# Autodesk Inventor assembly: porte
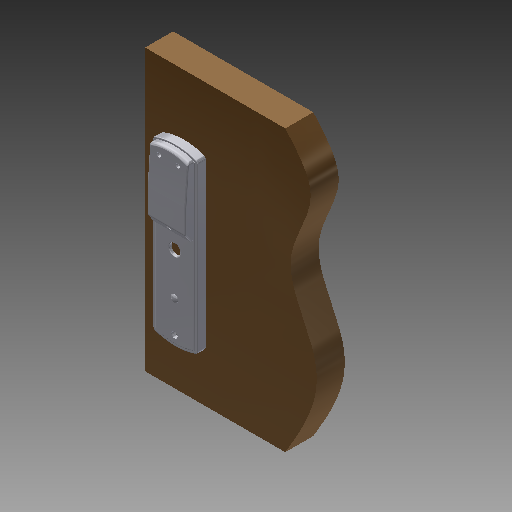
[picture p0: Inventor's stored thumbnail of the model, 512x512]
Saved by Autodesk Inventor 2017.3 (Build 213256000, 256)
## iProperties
Created: 2011-01
Part Number: porte
Material: Générique
Document SubType Name: Assembly
Designer: ficho
Author: ficho
Sending System: SolidWorks 2009
Last Author: christophe
Last Saved: 2011-02-11
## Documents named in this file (15)
- G:\travail\année 2019-2020\réforme\toussaint\Serrure biométrique SET\Documentations_pedagogique\Modelisation_Solidworks\porte.iam
- G:\travail\année 2019-2020\réforme\toussaint\Serrure biométrique SET\Documentations_pedagogique\Modelisation_Solidworks\capteur.iam
- G:\travail\année 2019-2020\réforme\toussaint\Serrure biométrique SET\Documentations_pedagogique\Modelisation_Solidworks\Assemblage9.iam
- G:\travail\année 2019-2020\réforme\toussaint\Serrure biométrique SET\Documentations_pedagogique\Modelisation_Solidworks\tetiere.iam
- G:\travail\année 2019-2020\réforme\toussaint\Serrure biométrique SET\Documentations_pedagogique\Modelisation_Solidworks\Assemblage5.iam
- G:\travail\année 2019-2020\réforme\toussaint\Serrure biométrique SET\Documentations_pedagogique\Modelisation_Solidworks\Pièce18.ipt
- G:\travail\année 2019-2020\réforme\toussaint\Serrure biométrique SET\Documentations_pedagogique\Modelisation_Solidworks\vis1.ipt
- G:\travail\année 2019-2020\réforme\toussaint\Serrure biométrique SET\Documentations_pedagogique\Modelisation_Solidworks\vis2.ipt
- G:\travail\année 2019-2020\réforme\toussaint\Serrure biométrique SET\Documentations_pedagogique\Modelisation_Solidworks\vis5.ipt
- G:\travail\année 2019-2020\réforme\toussaint\Serrure biométrique SET\Documentations_pedagogique\Modelisation_Solidworks\Pièce35.ipt
- G:\travail\année 2019-2020\réforme\toussaint\Serrure biométrique SET\Documentations_pedagogique\Modelisation_Solidworks\Pièce6.ipt
- G:\travail\année 2019-2020\réforme\toussaint\Serrure biométrique SET\Documentations_pedagogique\Modelisation_Solidworks\Pièce13.ipt
- G:\travail\année 2019-2020\réforme\toussaint\Serrure biométrique SET\Documentations_pedagogique\Modelisation_Solidworks\Assemblage a3.iam
- G:\travail\année 2019-2020\réforme\toussaint\Serrure biométrique SET\Documentations_pedagogique\Modelisation_Solidworks\porte.ipt
- G:\travail\année 2019-2020\réforme\toussaint\Serrure biométrique SET\Documentations_pedagogique\Modelisation_Solidworks\Pièce19.ipt
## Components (23 placed, 14 different names)
1. capteur:1 [sub-assembly]
2. Assemblage9:1 [sub-assembly]
3. tetiere:1 [sub-assembly]
4. Assemblage5:1 [sub-assembly]
5. Pièce18:1
6. vis1:1
7. vis1:2
8. vis1:3
9. vis1:4
10. vis1:5
11. vis1:6
12. vis1:7
13. vis1:8
14. vis1:9
15. vis2:1
16. vis2:2
17. vis5:1
18. Pièce35:1
19. Pièce6:1
20. Pièce13:1
21. Assemblage a3:2 [sub-assembly]
22. porte:2
23. Pièce19:1
